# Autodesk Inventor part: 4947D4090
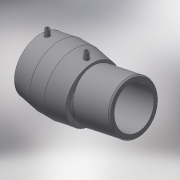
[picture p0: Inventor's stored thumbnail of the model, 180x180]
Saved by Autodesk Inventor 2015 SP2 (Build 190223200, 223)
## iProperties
Created: 2017-06
Part Number: 4947D4090
Material: Generic
Description: PLASSON ADJUSTABLE ELBOW (ONE SIDE) 90
Document SubType Name: Modeling
Designer: KIM
Mass: 983.781 g
Surface Area: 1626.67 cm^2
Volume: 983.781 cm^3
Density: 1 g/cm^3
Appearance: Default
Author: KIM
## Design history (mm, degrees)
derived "4947D4.ipt"
feature "Solid1::4947D4.ipt"
tag "TaggingFeature1"
body "Solid1"
other parameters: "d0" = 135.45, "d2" = 116, "d3" = 72, "d4" = 36, "d5" = 104.4, "d8" = 168 deg, "d10" = 28.8, "d11" = 9.6, "d29" = 77, "d30" = 15, "d31" = 51.6, "d34" = 5 deg, "d41" = 4, "d42" = 14, "d43" = 0, "d48" = 81, "d55" = 38.07, "d57" = 168 deg, "d62" = 3, "d63" = 0, "d65" = 258, "d67" = 81, "d68" = 135 deg, "d69" = 82, "d70" = 42.92, "d71" = 2.32, "L_" = 258, "L_1" = 72, "D_" = 116, "A_" = 77, "d_2" = 12, "L_0" = 148, "L_2" = 82, "d54" = 63.45, "d59" = 161.3813
